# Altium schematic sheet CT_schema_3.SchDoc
size 298 x 247 mm
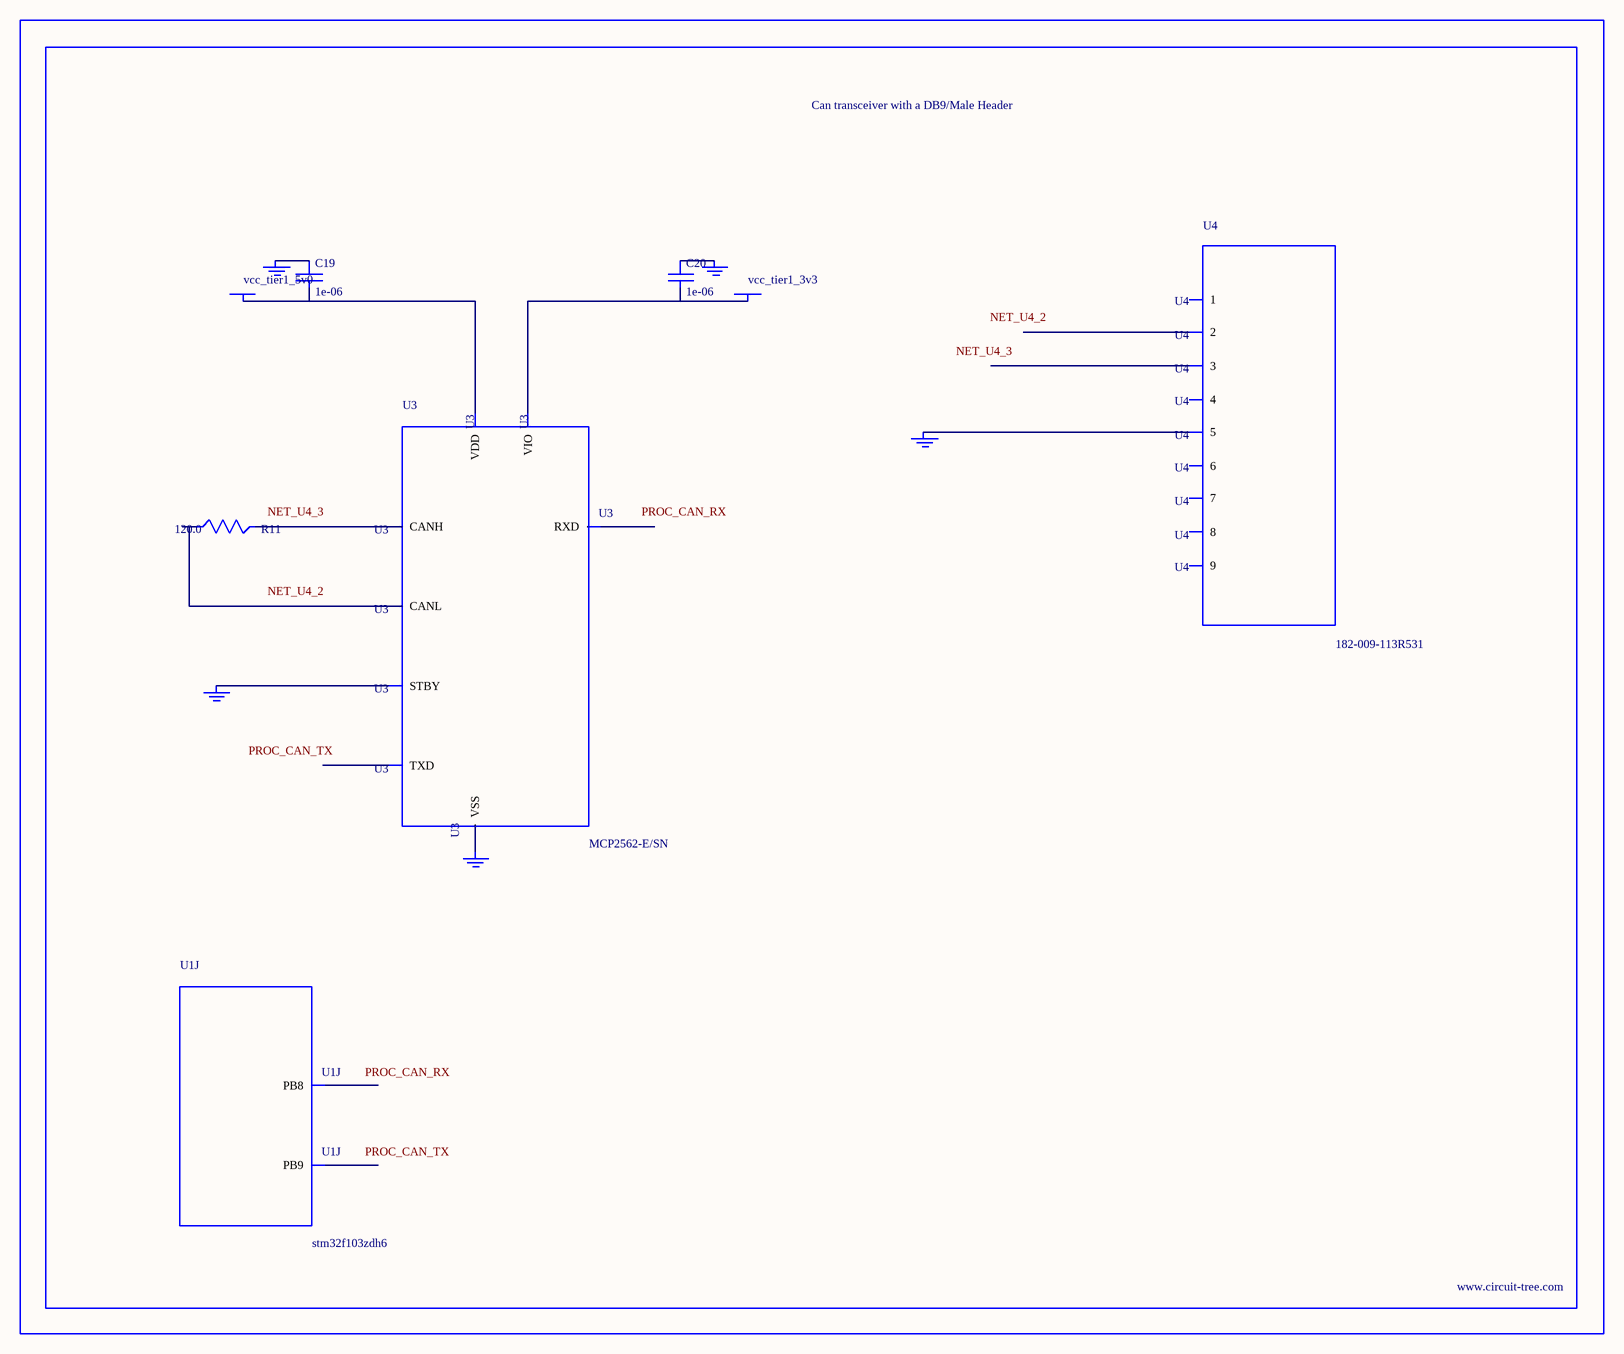
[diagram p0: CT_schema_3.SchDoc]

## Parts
BORDER2  (no value)
C19  1e-06  [C0603]
C20  1e-06  [C0603]
GND_INSTANCE_2_0  (no value)
GND_INSTANCE_2_1  (no value)
GND_INSTANCE_2_2  (no value)
GND_INSTANCE_2_3  (no value)
GND_INSTANCE_2_4  (no value)
POWER_INSTANCE_2_0  vcc_tier1_5v0
POWER_INSTANCE_2_1  vcc_tier1_3v3
R11  120.0  [R0603]
U1  stm32f103zdh6  [LFBGA144]  (part J of 12)
U3  MCP2562-E/SN  [SOIC-8]
U4  182-009-113R531  [182-009-MALE]

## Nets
NetC19_1: C19.1 GND_INSTANCE_2_0.0(GND)
NetC19_2: C19.2 POWER_INSTANCE_2_0.0(PWR) U3.3(VDD)
NetC20_1: C20.1 GND_INSTANCE_2_1.0(GND)
NetC20_2: C20.2 POWER_INSTANCE_2_1.0(PWR) U3.5(VIO)
NetGND_INSTANCE_2_2_0: GND_INSTANCE_2_2.0(GND) U3.8(STBY)
NetGND_INSTANCE_2_3_0: GND_INSTANCE_2_3.0(GND) U3.2(VSS)
NetGND_INSTANCE_2_4_0: GND_INSTANCE_2_4.0(GND) U4.5
NetR11_1: R11.1 U3.6(CANL)
NetR11_2: R11.2 U3.7(CANH)

Not connected (* = marked no-connect by the designer): U1 B5(PB9) C5(PB8); U3 1(TXD) 4(RXD); U4 1 2 3 4 6 7 8 9

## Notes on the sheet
- Labels drawn without touching a wire or pin: NET_U4_2, NET_U4_3, PROC_CAN_RX, PROC_CAN_TX

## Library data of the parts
BORDER2 = BORDER_PAGE2
C19 C20 = C0603C105K3RACTU
GND_INSTANCE_2_0-GND_INSTANCE_2_4 = GND
POWER_INSTANCE_2_0 POWER_INSTANCE_2_1 = PWR
R11 = RC0603JR-07120RL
